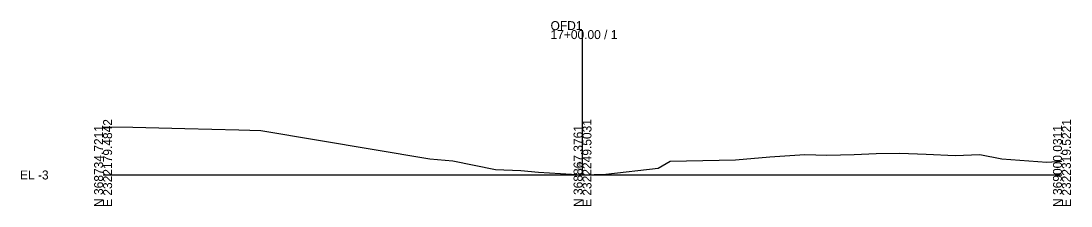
# Model space of a CAD drawing. Extents: x -26 to 303, y -10 to 14048.
# Drawn here: x -25.7 to 302.8, y 13990.3 to 14048.1 of the extents above; entities that cross this region are included whole.
import ezdxf

# ---------------------------------------------------------------- set-up
doc = ezdxf.new("R2010")
doc.units = 0
for name, color, linetype in [('RD_GPK_XS_Cell', 7, 'Continuous'), ('RD_XS_ExGround', 7, 'Continuous'), ('RD_XS_TX_Elev_EX', 7, 'Continuous')]:
    doc.layers.add(name, color=color, linetype=linetype)

msp = doc.modelspace()

# ---------------------------------------------------------------- linework, layer by layer
at = {"layer": 'RD_GPK_XS_Cell'}
for p, q in [((150, 14000), (150, 14045.3)), ((0, 14000), (150, 14000)), ((150, 14000), (300, 14000))]:
    msp.add_line(p, q, dxfattribs=at)
at = {"layer": 'RD_XS_ExGround'}
for p, q in [((0, 14015.1), (9.33, 14014.96)), ((9.33, 14014.96), (25.62, 14014.51)), ((25.62, 14014.51), (42.42, 14014.12)), ((42.42, 14014.12), (49.38, 14013.9)), ((49.38, 14013.9), (102.21, 14005.06)), ((197.82, 14004.72), (208.57, 14005.7)), ((208.57, 14005.7), (219.53, 14006.36)), ((219.53, 14006.36), (226.46, 14006.21)), ((226.46, 14006.21), (235, 14006.42)), ((235, 14006.42), (241.93, 14006.72)), ((241.93, 14006.72), (249.26, 14006.77)), ((249.26, 14006.77), (257.55, 14006.54)), ((257.55, 14006.54), (266.58, 14006.14)), ((266.58, 14006.14), (274.36, 14006.42)), ((274.36, 14006.42), (281.16, 14005.07)), ((102.21, 14005.06), (109.46, 14004.45)), ((109.46, 14004.45), (122.74, 14001.69)), ((157.3, 14000.23), (173.67, 14002.13)), ((173.67, 14002.13), (177.43, 14004.36)), ((177.43, 14004.36), (197.82, 14004.72)), ((281.16, 14005.07), (295.29, 14003.96)), ((295.29, 14003.96), (300, 14004.29)), ((122.74, 14001.69), (130.66, 14001.43)), ((130.66, 14001.43), (136.24, 14000.93)), ((136.24, 14000.93), (150, 14000.04)), ((150, 14000.04), (157.3, 14000.23))]:
    msp.add_line(p, q, dxfattribs=at)

# ---------------------------------------------------------------- texts
at = {"layer": 'RD_GPK_XS_Cell'}
for s, p in [('OFD1', (140, 14045.3)), ('17+00.00 / 1', (140, 14042.5)), ('EL -3', (-26, 13998.6))]:
    msp.add_text(s, height=2.8, dxfattribs=at).set_placement(p)
for s, p in [('N 368734.7211', (0, 13990)), ('E 2322179.4842', (2.8, 13990)), ('N 368867.3761', (150, 13990)), ('E 2322249.5031', (152.8, 13990)), ('N 369000.0311', (300, 13990)), ('E 2322319.5221', (302.8, 13990))]:
    msp.add_text(s, height=2.8, rotation=90, dxfattribs=at).set_placement(p)
at = {"layer": 'RD_XS_TX_Elev_EX'}
msp.add_text('-2.96', height=1, rotation=90, dxfattribs=at).set_placement((149.5, 14001.04))

doc.saveas('drawing.dxf')
